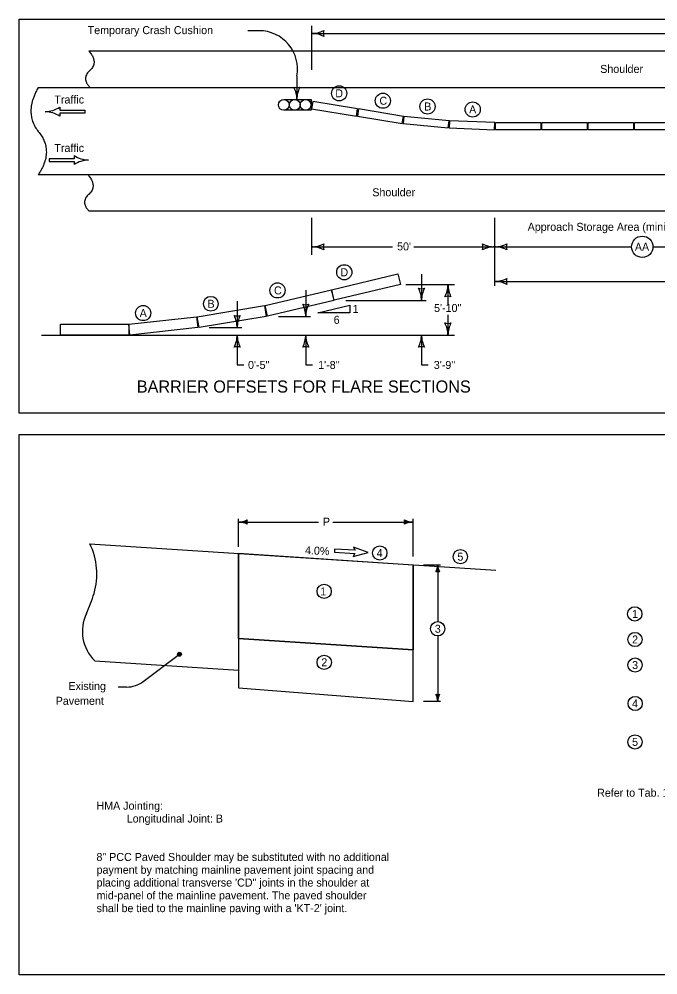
# Model space of a CAD drawing. Extents: x 10133 to 81668, y 5848 to 11018.
# Drawn here: x 13752 to 14807, y 5848 to 7424 of the extents above; entities that cross this region are included whole.
import ezdxf

# ---------------------------------------------------------------- set-up
doc = ezdxf.new("R2010")
doc.units = 0
doc.layers.add('SheetText', color=7, linetype='Continuous')

msp = doc.modelspace()

# ---------------------------------------------------------------- linework, layer by layer
at = {"layer": 'SheetText'}
for p, q in [((13752.2, 7424.4), (16857.2, 7424.4)), ((13752.2, 6774.4), (13752.2, 7424.4)), ((14235.1, 7413.5), (14235.1, 7340.9)), ((14148.6, 7405.2), (14129.9, 7405.2)), ((14235.1, 7400.7), (15168, 7400.7)), ((13867.5, 7371.8), (14996, 7371.8)), ((14210.8, 7330.5), (14210.8, 7291.9)), ((13783.9, 7311.8), (15026, 7311.8)), ((14189.2, 7291.9), (14234.2, 7291.9)), ((14234.2, 7291.9), (14234.2, 7273.9)), ((13795.4, 7271.7), (13795.4, 7271.7)), ((13819.3, 7279.2), (13819.3, 7273.9)), ((13819.3, 7273.9), (13860.5, 7273.9)), ((13860.5, 7269.4), (13819.3, 7269.4)), ((13819.3, 7269.4), (13819.3, 7264.2)), ((13860.5, 7273.9), (13860.5, 7269.4)), ((14234.2, 7273.9), (14189.2, 7273.9)), ((14233, 7279.6), (14234.3, 7279.3)), ((14234.8, 7275.9), (14234.8, 7275.9)), ((13842.9, 7194), (13801.7, 7194)), ((13801.7, 7194), (13801.7, 7189.5)), ((13842.9, 7199.3), (13842.9, 7194)), ((13866.8, 7191.8), (13866.8, 7191.8)), ((13801.7, 7189.5), (13842.9, 7189.5)), ((13842.9, 7189.5), (13842.9, 7184.3)), ((13783.9, 7167.8), (15026, 7167.8)), ((13867.5, 7107.8), (14996, 7107.8)), ((14235.1, 7096.5), (14235.1, 7035.3)), ((14537.3, 7096.5), (14537.3, 6984.1)), ((14235.1, 7048.7), (14368.5, 7048.7)), ((14403.8, 7048.7), (14537.3, 7048.7)), ((14537.3, 7048.7), (14763.4, 7048.7)), ((14798.7, 7048.7), (15024.8, 7048.7)), ((14416.5, 7003.8), (14416.5, 6960.4)), ((14390.6, 6986.3), (14471, 6986.3)), ((14460.2, 6986.3), (14460.2, 6952.9)), ((14537.3, 6991.6), (15128.1, 6991.6)), ((14225.4, 6977.4), (14225.4, 6934)), ((14112.2, 6958.9), (14112.2, 6915.4)), ((14291.7, 6960.4), (14424.3, 6960.4)), ((14245.5, 6940), (14298.1, 6952.4)), ((14298.1, 6940), (14245.5, 6940)), ((14298.1, 6952.4), (14298.1, 6940)), ((14180.4, 6934), (14233.1, 6934)), ((14460.2, 6936.5), (14460.2, 6903.1)), ((14066.2, 6915.4), (14119.9, 6915.4)), ((13789.1, 6903.1), (14471, 6903.1)), ((14112.2, 6903.1), (14112.2, 6876.1)), ((14225.4, 6903.1), (14225.4, 6853.8)), ((14416.5, 6903.1), (14416.5, 6853.8)), ((14112.2, 6876.1), (14112.2, 6853.8)), ((14112.2, 6853.8), (14123.3, 6853.8)), ((14225.4, 6853.8), (14236.5, 6853.8)), ((14416.5, 6853.8), (14427.7, 6853.8)), ((16857.2, 6774.4), (13752.2, 6774.4)), ((14114.2, 6553.9), (14114.2, 6600.2)), ((14114.2, 6594.6), (14128, 6594.6)), ((14114.2, 6594.6), (14246.5, 6594.6)), ((14270.4, 6594.6), (14402.7, 6594.6)), ((14402.7, 6594.6), (14388.8, 6594.6)), ((14402.7, 6537.9), (14402.7, 6600.2)), ((13868.8, 6558.9), (14539.1, 6515.5)), ((14420, 6524.3), (14448, 6524.3)), ((14443.3, 6524.3), (14443.3, 6512.9)), ((14443.3, 6524.3), (14443.3, 6430.3)), ((14114.2, 6402.6), (14402.7, 6384)), ((14443.3, 6406.8), (14443.3, 6298.8)), ((13957, 6331.8), (14017.1, 6376.7)), ((13877, 6365.6), (14114.2, 6350.2)), ((13929.6, 6322.4), (13915.5, 6322.4)), ((14443.3, 6298.8), (14443.3, 6310.2)), ((14448, 6298.8), (14420, 6298.8))]:
    msp.add_line(p, q, dxfattribs=at)
for points in [[(14311.1, 7276.3), (14237, 7288.4), (14235.1, 7276.6), (14309.1, 7264.5)], [(14386.6, 7263.9), (14312.5, 7276.1), (14310.6, 7264.2), (14384.6, 7252.1)], [(14462, 7256.7), (14387.3, 7263.8), (14386.2, 7251.9), (14460.8, 7244.8)], [(14537.7, 7253.8), (14462.8, 7256.8), (14462.3, 7244.8), (14537.3, 7241.8)], [(14538.5, 7253.8), (14613.5, 7253.8), (14613.5, 7241.8), (14538.5, 7241.8)], [(14615, 7253.8), (14690, 7253.8), (14690, 7241.8), (14615, 7241.8)], [(14691.5, 7253.8), (14766.5, 7253.8), (14766.5, 7241.8), (14691.5, 7241.8)], [(14768, 7253.8), (14843, 7253.8), (14843, 7241.8), (14768, 7241.8)], [(14268.2, 6978), (14377.7, 7003.9), (14381.8, 6986.4), (14272.3, 6960.5)], [(14158.4, 6952), (14267.8, 6977.9), (14272, 6960.4), (14162.5, 6934.5)], [(14046.3, 6933.3), (14157.3, 6951.7), (14160.2, 6934), (14049.2, 6915.5)], [(13933.2, 6921), (14045, 6933.3), (14047, 6915.4), (13935.2, 6903.1)], [(13820.7, 6921.2), (13933.2, 6921.1), (13933.2, 6903.1), (13820.7, 6903.2)], [(13752.2, 6738.9), (15302.9, 6738.9), (15302.9, 5847.6), (13752.2, 5847.6)], [(14303.5, 6538), (14328.4, 6544.2), (14304.3, 6553.1), (14307, 6548), (14273.1, 6550.1), (14272.8, 6545), (14306.6, 6542.8)], [(14114.2, 6543.2), (14402.7, 6524.3), (14402.7, 6384), (14114.2, 6402.6)]]:
    msp.add_lwpolyline(points, close=True, dxfattribs=at)
for points in [[(14127.8, 6592), (14127.2, 6594.6), (14127.8, 6597.2), (14124.7, 6595.7), (14119.8, 6594.6), (14125, 6593.4), (14127.3, 6592.3), (14126.8, 6594.6), (14127, 6596.3), (14124.9, 6595.3), (14122.2, 6594.6), (14125.1, 6593.8), (14126.6, 6593.2), (14126.3, 6595.4), (14124.3, 6594.6), (14125.9, 6594.1), (14125.9, 6594.9), (14125.2, 6594.6)], [(14389.1, 6597.1), (14389.6, 6594.6), (14389.1, 6592), (14392.2, 6593.5), (14397.1, 6594.6), (14391.8, 6595.8), (14389.6, 6596.8), (14390.1, 6594.6), (14389.9, 6592.9), (14391.9, 6593.9), (14394.7, 6594.6), (14391.8, 6595.4), (14390.3, 6595.9), (14390.5, 6593.7), (14392.5, 6594.6), (14391, 6595.1), (14390.9, 6594.3), (14391.7, 6594.6)], [(14114.2, 6543.2), (14114.2, 6321.4), (14402.7, 6298.8), (14402.7, 6524.3)], [(14441.2, 6513.1), (14443.4, 6513.6), (14445.5, 6513.1), (14444.3, 6515.7), (14443.4, 6519.7), (14442.3, 6515.4), (14441.5, 6513.5), (14443.4, 6514), (14444.7, 6513.8), (14443.9, 6515.4), (14443.4, 6517.7), (14442.7, 6515.3), (14442.2, 6514.1), (14444.1, 6514.3), (14443.4, 6516), (14442.9, 6514.6), (14443.6, 6514.6), (14443.4, 6515.2)], [(14019.1, 6378.4), (14018, 6378.8), (14016.4, 6379.6), (14015, 6378.6), (14014.2, 6377.4), (14013.9, 6375.7), (14015.1, 6374.7), (14016.5, 6373.7), (14018, 6374.1), (14019.1, 6375), (14019.7, 6376.9), (14018.9, 6377.9), (14017.5, 6378.8), (14015.7, 6379), (14014.7, 6377.8), (14014.5, 6376.2), (14015.5, 6375.1), (14016.9, 6374.1), (14017.7, 6374.6), (14018.7, 6375.2), (14019.2, 6376.7), (14018.3, 6377.5), (14017.1, 6378.3), (14015.9, 6378.5), (14015.3, 6377.1), (14015.4, 6375.8), (14016.4, 6374.8), (14017.2, 6375.1), (14018.1, 6375.4), (14018.4, 6376.6), (14017.8, 6377.5), (14016.8, 6377.8), (14016.1, 6377.2), (14015.9, 6376.3), (14016.4, 6375.5), (14017, 6375.4), (14017.5, 6375.6), (14017.8, 6376.6), (14017.4, 6377.1), (14016.7, 6377.3), (14016.4, 6376.9), (14016.5, 6376.3), (14017, 6375.8), (14017.3, 6376.2), (14017.1, 6376.7)], [(14445.5, 6309.9), (14443.3, 6309.5), (14441.2, 6310), (14442.4, 6307.4), (14443.3, 6303.4), (14444.4, 6307.7), (14445.2, 6309.6), (14443.3, 6309.1), (14442, 6309.3), (14442.8, 6307.6), (14443.3, 6305.4), (14444, 6307.8), (14444.5, 6309), (14442.6, 6308.8), (14443.3, 6307.1), (14443.7, 6308.4), (14443.1, 6308.4), (14443.3, 6307.8)]]:
    msp.add_lwpolyline(points, dxfattribs=at)
for centre, radius in [((14280.6, 7301.9), 12.5), ((14352.8, 7289.7), 12.5), ((14189.2, 7282.9), 9), ((14189.2, 7282.9), 9), ((14207.2, 7282.9), 9), ((14207.2, 7282.9), 9), ((14225.2, 7282.9), 9), ((14225.2, 7282.9), 9), ((14426.5, 7280.2), 12.5), ((14501.1, 7275.3), 12.5), ((14781, 7048.7), 17.6), ((14289, 7006.7), 12.5), ((14178.7, 6976.8), 12.5), ((14068.7, 6954.7), 12.2), ((13957.1, 6939.4), 12.5), ((14347.7, 6543.6), 11.8), ((14480.7, 6537.5), 11.8), ((14255.8, 6480.4), 11.8), ((14768.6, 6443.1), 11.8), ((14443.3, 6418.6), 11.8), ((14768.9, 6400.9), 11.8), ((14016.9, 6376.5), 3.15), ((14255.9, 6363.3), 11.8), ((14769.1, 6358.7), 11.8), ((14769.3, 6295.3), 11.8), ((14769, 6231.9), 11.8)]:
    msp.add_circle(centre, radius, dxfattribs=at)
for centre, radius, start, end in [((14148.6, 7341.9), 63.3, 349.6463, 90), ((14235.1, 7443.2), 42.5, 270, 298.0725), ((14235.1, 7358.2), 42.5, 61.9275, 90), ((14270.7, 7400.7), 16.4, 162.2666, 197.7334), ((14210.8, 7327.5), 16.4, 252.2666, 287.7333), ((14168.3, 7291.9), 42.5, 360, 28.0725), ((14253.3, 7291.9), 42.5, 151.9275, 180), ((13793.4, 7320), 48.4, 272.352, 302.382), ((13793.4, 7223.3), 48.4, 57.618, 87.648), ((13868.8, 7240.1), 48.4, 237.618, 267.648), ((13868.8, 7143.5), 48.4, 92.352, 122.382), ((14235.1, 7091.2), 42.5, 270, 298.0725), ((14235.1, 7006.2), 42.5, 61.9275, 90), ((14270.7, 7048.7), 16.4, 162.2666, 197.7334), ((14501.6, 7048.7), 16.4, 342.2666, 17.7333), ((14537.3, 7091.2), 42.5, 241.9275, 270), ((14537.3, 7006.2), 42.5, 90, 118.0725), ((14537.3, 7091.2), 42.5, 270, 298.0725), ((14537.3, 7006.2), 42.5, 61.9275, 90), ((14572.9, 7048.7), 16.4, 162.2666, 197.7334), ((14417.7, 6986.3), 42.5, 331.9275, 360), ((14502.7, 6986.3), 42.5, 180, 208.0725), ((14537.3, 7034.1), 42.5, 270, 298.0725), ((14537.3, 6949.1), 42.5, 61.9275, 90), ((14572.9, 6991.6), 16.4, 162.2666, 197.7334), ((14416.5, 6996), 16.4, 252.2666, 287.7333), ((14374, 6960.4), 42.5, 360, 28.0725), ((14459, 6960.4), 42.5, 151.9275, 180), ((14225.4, 6969.6), 16.4, 252.2666, 287.7333), ((14182.9, 6934), 42.5, 360, 28.0725), ((14267.9, 6934), 42.5, 151.9275, 180), ((14460.2, 6950.7), 16.4, 72.2666, 107.7334), ((14112.2, 6951), 16.4, 252.2666, 287.7333), ((14069.7, 6915.4), 42.5, 360, 28.0725), ((14154.7, 6915.4), 42.5, 151.9275, 180), ((14460.2, 6938.7), 16.4, 252.2666, 287.7333), ((14417.7, 6903.1), 42.5, 360, 28.0725), ((14502.7, 6903.1), 42.5, 151.9275, 180), ((14069.7, 6903.1), 42.5, 331.9275, 360), ((14154.7, 6903.1), 42.5, 180, 208.0725), ((14182.9, 6903.1), 42.5, 331.9275, 360), ((14267.9, 6903.1), 42.5, 180, 208.0725), ((14374, 6903.1), 42.5, 331.9275, 360), ((14459, 6903.1), 42.5, 180, 208.0725), ((14112.2, 6867.4), 16.4, 72.2666, 107.7334), ((14225.4, 6867.4), 16.4, 72.2666, 107.7334), ((14416.5, 6867.4), 16.4, 72.2666, 107.7334), ((14114.2, 6625.2), 30.6, 270, 298.0725), ((14114.2, 6564), 30.6, 61.9275, 90), ((14139.9, 6594.6), 11.8, 162.2666, 197.7334), ((14377, 6594.6), 11.8, 342.2666, 17.7334), ((14402.7, 6625.2), 30.6, 241.9275, 270), ((14402.7, 6564), 30.6, 90, 118.0725), ((13767.6, 6508.7), 113, 343.6708, 26.3373), ((14418.1, 6524.3), 25.2, 331.9275, 360), ((14443.3, 6503.1), 9.75, 72.2666, 107.7334), ((14468.6, 6524.3), 25.2, 180, 208.0725), ((13663.5, 6539.2), 221.4, 334.4332, 343.6708), ((13924.8, 6414.3), 68.2, 154.4332, 225.5564), ((13929.6, 6367.4), 45, 270, 307.6187), ((14443.3, 6319.9), 9.75, 252.2666, 287.7334), ((14418.1, 6298.8), 25.2, 360, 28.0725), ((14468.6, 6298.8), 25.2, 151.9275, 180)]:
    msp.add_arc(centre, radius, start, end, dxfattribs=at)
for points in [[(13867.5, 7371.8), (13883.5, 7352.5), (13854.6, 7326.9), (13869.1, 7311.8)], [(13783.9, 7311.8), (13759.2, 7269.1), (13810, 7207), (13783.9, 7167.8)], [(13865.9, 7167.8), (13881.9, 7148.4), (13853, 7122.8), (13867.5, 7107.8)]]:
    msp.add_open_spline(points, degree=2, dxfattribs=at)

# ---------------------------------------------------------------- texts
for s, height, p in [('Temporary Crash Cushion', 13.2, (13865.4, 7399.6)), ('Shoulder', 13.2, (14711.6, 7335.6)), ('D', 13.2, (14274.2, 7295.3)), ('Traffic', 13.2, (13810.4, 7285.1)), ('C', 13.2, (14347.1, 7283.1)), ('B', 13.2, (14421.1, 7273.6)), ('A', 13.2, (14495.2, 7268.7)), ('Traffic', 13.2, (13810.4, 7205.2)), ('Shoulder', 13.2, (14335.3, 7132.1)), ("Approach Storage Area (minimum 20')", 13.2, (14591.8, 7075.1)), ("50'", 13.2, (14376.2, 7042.8)), ('AA', 13.2, (14768.8, 7042.1)), ('D', 13.2, (14282.7, 7000.1)), ('C', 13.2, (14173, 6970.2)), ('B', 13.2, (14063.2, 6948.1)), ("5'-10''", 13.2, (14437.3, 6941.2)), ('A', 13.2, (13951.2, 6932.8)), ('1', 13.2, (14302.7, 6939.7)), ('6', 13.2, (14271.5, 6921.7)), ("0'-5''", 13.2, (14130.1, 6847.2)), ("1'-8''", 13.2, (14245.9, 6847.2)), ("3'-9''", 13.2, (14436.8, 6847.2)), ('BARRIER OFFSETS FOR FLARE SECTIONS', 20, (13946.5, 6808.2)), ('P', 13.2, (14253.8, 6588.6)), ('4', 13.2, (14342.5, 6537)), ('5', 13.2, (14475.8, 6530.9)), ('1', 13.2, (14249.2, 6473.5)), ('1', 13.2, (14764.2, 6436.5)), ('3', 13.2, (14438.5, 6412)), ('2', 13.2, (14764.2, 6394.3)), ('2', 13.2, (14251.2, 6356.7)), ('3', 13.2, (14764.2, 6352.1)), ('Existing', 13.2, (13833.7, 6317.5)), ('Pavement', 13.2, (13812.6, 6293.1)), ('4', 13.2, (14764.2, 6288.7)), ('5', 13.2, (14764.2, 6225.3)), ('Refer to Tab. 112-9 for P width and Shoulder quantities', 13.2, (14706.5, 6141.5)), ('HMA Jointing:', 13.2, (13879.9, 6120)), ('Longitudinal Joint: B', 13.2, (13929.9, 6098.9)), ('8" PCC Paved Shoulder may be substituted with no additional ', 13.2, (13879.9, 6035.5)), ('payment by matching mainline pavement joint spacing and ', 13.2, (13880.1, 6014.4)), ('placing additional transverse \'CD" joints in the shoulder at ', 13.2, (13880.1, 5993.3)), ('mid-panel of the mainline pavement. The paved shoulder ', 13.2, (13880.1, 5972.2)), ("shall be tied to the mainline paving with a 'KT-2' joint.", 13.2, (13880.1, 5951.1))]:
    msp.add_text(s, height=height, dxfattribs=at).set_placement(p)
msp.add_text('4.0%', height=13.2, rotation=357.4961, dxfattribs=at).set_placement((14224, 6541.7))

doc.saveas('drawing.dxf')
